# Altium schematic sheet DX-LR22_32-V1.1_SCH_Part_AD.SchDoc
size 431 x 279 mm; SchematicName: $$$NONE
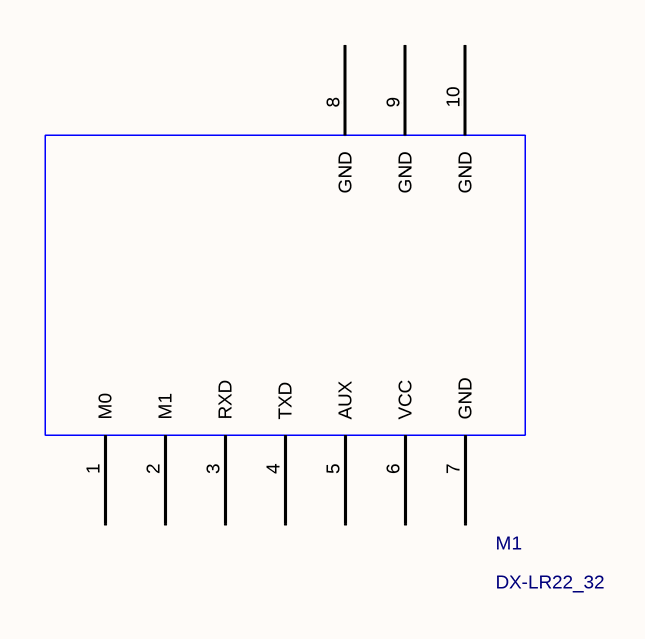
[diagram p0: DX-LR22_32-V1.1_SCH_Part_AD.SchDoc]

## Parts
M1  DX-LR22_32  [DX-LR02]

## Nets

Not connected (* = marked no-connect by the designer): M1 1(M0) 2(M1) 3(RXD) 4(TXD) 5(AUX) 6(VCC) 7(GND) 8(GND) 9(GND) 10(GND)

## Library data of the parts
M1 = DX-LR02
